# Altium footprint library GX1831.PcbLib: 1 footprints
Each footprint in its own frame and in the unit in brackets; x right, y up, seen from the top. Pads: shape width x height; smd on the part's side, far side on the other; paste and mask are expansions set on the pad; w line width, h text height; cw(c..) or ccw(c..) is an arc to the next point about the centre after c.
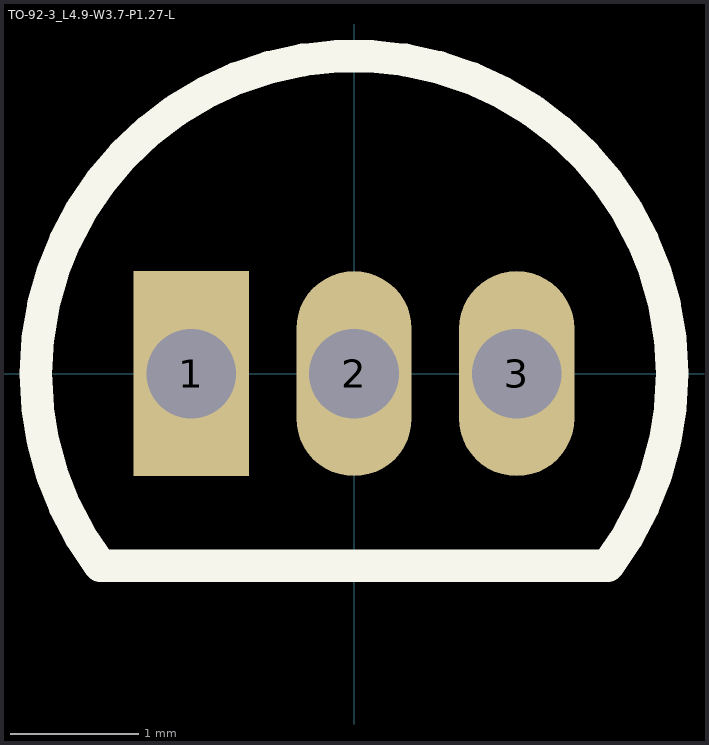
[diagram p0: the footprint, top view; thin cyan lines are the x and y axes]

## TO-92-3_L4.9-W3.7-P1.27-L [mm]
pads (3):
  rect 0.9x1.6 hole 0.7: 1(-1.27,0)
  oval 0.9x1.6 hole 0.7: 2(0,0) 3(1.27,0)
Top Overlay:
  lines w0.254: -1.981,-1.501 cw(c0,-0.003) 1.981,-1.501 ; -1.98,-1.5 1.98,-1.5
3D body "TO-92.STEP": height 5.6, standoff -5, extent -2.3,-1.34 2.3,2.261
